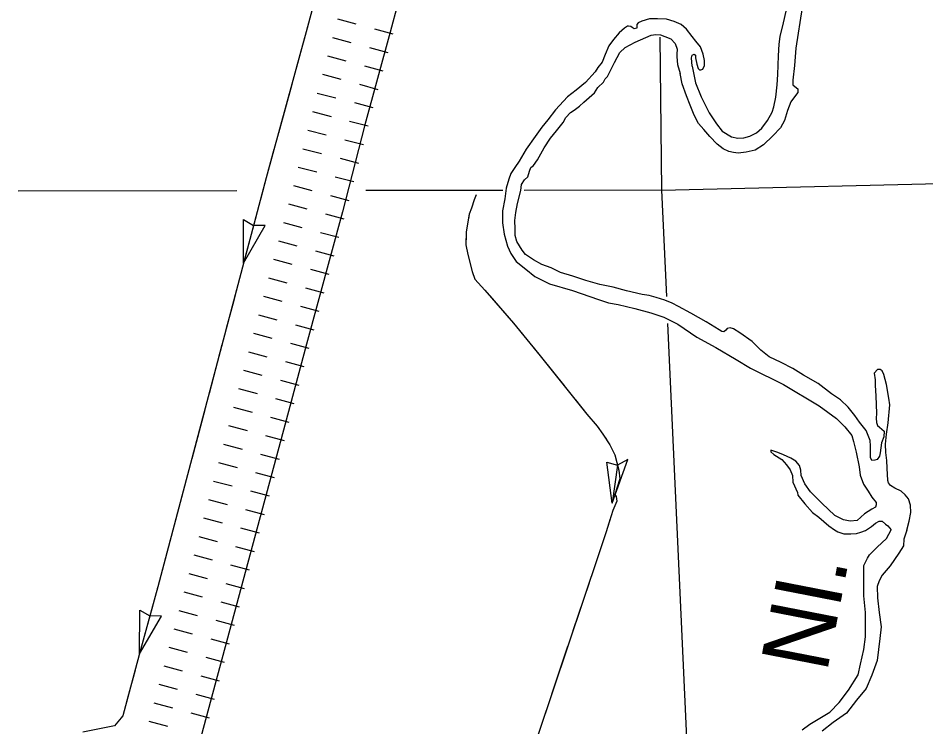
# Model space of a CAD drawing. Extents: x 1164457 to 1439835, y 1590918 to 1773502.
# Drawn here: x 1319420 to 1326531, y 1641151 to 1646706 of the extents above; entities that cross this region are included whole.
import ezdxf

# ---------------------------------------------------------------- set-up
doc = ezdxf.new("R2010")
doc.units = 0
for name, color, linetype in [('Level 29', 7, 'Continuous'), ('Level 35', 7, 'Continuous'), ('Level 43', 7, 'Continuous'), ('Level 5', 7, 'Continuous')]:
    doc.layers.add(name, color=color, linetype=linetype)

msp = doc.modelspace()

# ---------------------------------------------------------------- linework, layer by layer
at = {"layer": 'Level 29'}
for p, q in [((1321922, 1646700.6), (1322066.8, 1646661.2)), ((1322211.5, 1646621.8), (1322356.2, 1646582.4)), ((1321882.6, 1646555.9), (1322027.3, 1646516.5)), ((1321882.6, 1646555.9), (1322027.3, 1646516.5)), ((1322172.1, 1646477.1), (1322316.8, 1646437.7)), ((1322172.1, 1646477.1), (1322316.8, 1646437.7)), ((1321843.2, 1646411.1), (1321987.9, 1646371.7)), ((1322132.7, 1646332.3), (1322277.4, 1646292.9)), ((1321803.8, 1646266.4), (1321948.5, 1646227)), ((1322093.3, 1646187.6), (1322238, 1646148.2)), ((1321763.7, 1646118.7), (1321909, 1646081.3)), ((1321763.7, 1646118.7), (1321909, 1646081.3)), ((1322054.2, 1646043.8), (1322199.5, 1646006.4)), ((1322054.2, 1646043.8), (1322199.5, 1646006.4)), ((1321726.3, 1645973.5), (1321871.5, 1645936)), ((1322016.8, 1645898.6), (1322162, 1645861.1)), ((1321688.8, 1645828.2), (1321834.1, 1645790.8)), ((1321979.3, 1645753.3), (1322124.6, 1645715.9)), ((1321651.4, 1645683), (1321796.6, 1645645.5)), ((1321651.4, 1645683), (1321796.6, 1645645.5)), ((1321941.9, 1645608.1), (1322087.1, 1645570.6)), ((1321941.9, 1645608.1), (1322087.1, 1645570.6)), ((1321613.9, 1645537.7), (1321759.2, 1645500.3)), ((1321904.4, 1645462.8), (1322049.7, 1645425.4)), ((1321576.6, 1645395.1), (1321721.4, 1645356)), ((1321866.2, 1645316.9), (1322011, 1645277.8)), ((1321537.5, 1645250.3), (1321682.3, 1645211.2)), ((1321537.5, 1645250.3), (1321682.3, 1645211.2)), ((1321827.1, 1645172.1), (1321971.9, 1645133)), ((1321827.1, 1645172.1), (1321971.9, 1645133)), ((1321498.4, 1645105.4), (1321643.2, 1645066.4)), ((1321788, 1645027.3), (1321932.8, 1644988.2)), ((1321459.3, 1644960.6), (1321604.1, 1644921.5)), ((1321748.9, 1644882.4), (1321893.8, 1644843.4)), ((1321420.2, 1644815.8), (1321565, 1644776.7)), ((1321420.2, 1644815.8), (1321565, 1644776.7)), ((1321709.9, 1644737.6), (1321854.7, 1644698.5)), ((1321709.9, 1644737.6), (1321854.7, 1644698.5)), ((1321381.1, 1644671), (1321526, 1644631.9)), ((1321670.8, 1644592.8), (1321815.6, 1644553.7)), ((1321342.1, 1644526.2), (1321486.9, 1644487.1)), ((1321631.7, 1644448), (1321776.5, 1644408.9)), ((1321303, 1644381.3), (1321447.8, 1644342.3)), ((1321303, 1644381.3), (1321447.8, 1644342.3)), ((1321592.6, 1644303.2), (1321737.4, 1644264.1)), ((1321592.6, 1644303.2), (1321737.4, 1644264.1)), ((1321263.9, 1644236.5), (1321408.7, 1644197.4)), ((1321553.5, 1644158.4), (1321698.4, 1644119.3)), ((1321224.8, 1644091.7), (1321369.6, 1644052.6)), ((1321185.8, 1643946.9), (1321330.6, 1643907.8)), ((1321185.8, 1643946.9), (1321330.6, 1643907.8)), ((1321514.5, 1644013.5), (1321659.3, 1643974.5)), ((1321146.7, 1643802), (1321291.5, 1643763)), ((1321475.4, 1643868.7), (1321620.2, 1643829.6)), ((1321475.4, 1643868.7), (1321620.2, 1643829.6)), ((1321436.3, 1643723.9), (1321581.1, 1643684.8)), ((1321107.6, 1643657.1), (1321252.5, 1643618.1)), ((1321397.3, 1643579.1), (1321542.1, 1643540.1)), ((1321068.6, 1643512.3), (1321213.4, 1643473.3)), ((1321068.6, 1643512.3), (1321213.4, 1643473.3)), ((1321358.3, 1643434.3), (1321503.1, 1643395.2)), ((1321358.3, 1643434.3), (1321503.1, 1643395.2)), ((1321029.6, 1643367.5), (1321174.4, 1643328.4)), ((1321319.3, 1643289.4), (1321464.1, 1643250.4)), ((1320990.6, 1643222.6), (1321135.4, 1643183.6)), ((1321280.2, 1643144.6), (1321425.1, 1643105.6)), ((1320951.6, 1643077.8), (1321096.4, 1643038.8)), ((1320951.6, 1643077.8), (1321096.4, 1643038.8)), ((1321241.2, 1642999.7), (1321386.1, 1642960.7)), ((1321241.2, 1642999.7), (1321386.1, 1642960.7)), ((1320912.5, 1642932.9), (1321057.4, 1642893.9)), ((1321202.2, 1642854.9), (1321347, 1642815.9)), ((1320873.5, 1642788.1), (1321018.3, 1642749.1)), ((1321163.2, 1642710.1), (1321308, 1642671.1)), ((1320834.5, 1642643.3), (1320979.3, 1642604.3)), ((1320834.5, 1642643.3), (1320979.3, 1642604.3)), ((1321124.2, 1642565.2), (1321269, 1642526.2)), ((1321124.2, 1642565.2), (1321269, 1642526.2)), ((1320795.5, 1642498.4), (1320940.3, 1642459.4)), ((1321085.1, 1642420.4), (1321230, 1642381.4)), ((1320756.5, 1642353.6), (1320901.3, 1642314.6)), ((1321046.1, 1642275.6), (1321191, 1642236.5)), ((1320717.4, 1642208.8), (1320862.3, 1642169.7)), ((1320717.4, 1642208.8), (1320862.3, 1642169.7)), ((1321007.1, 1642130.7), (1321151.9, 1642091.7)), ((1321007.1, 1642130.7), (1321151.9, 1642091.7)), ((1320678.4, 1642063.9), (1320823.3, 1642024.9)), ((1320968.1, 1641985.9), (1321112.9, 1641946.9)), ((1320639.4, 1641919.1), (1320784.2, 1641880.1)), ((1320929.1, 1641841.1), (1321073.9, 1641802)), ((1320600.4, 1641774.3), (1320745.2, 1641735.2)), ((1320600.4, 1641774.3), (1320745.2, 1641735.2)), ((1320890.1, 1641696.2), (1321034.9, 1641657.2)), ((1320890.1, 1641696.2), (1321034.9, 1641657.2)), ((1320561.4, 1641629.4), (1320706.2, 1641590.4)), ((1320851, 1641551.4), (1320995.9, 1641512.4)), ((1320522.3, 1641484.6), (1320667.2, 1641445.6)), ((1320812, 1641406.6), (1320956.8, 1641367.5)), ((1320483.3, 1641339.8), (1320628.2, 1641300.7)), ((1320483.3, 1641339.8), (1320628.2, 1641300.7)), ((1320773, 1641261.7), (1320917.8, 1641222.7)), ((1320773, 1641261.7), (1320917.8, 1641222.7)), ((1320444.3, 1641194.9), (1320589.1, 1641155.9))]:
    msp.add_line(p, q, dxfattribs=at)
msp.add_lwpolyline([(1323235.6, 1649937.1), (1323120.9, 1649505.5), (1322642.8, 1647750), (1322454.2, 1647047.5), (1322333.9, 1646596.3), (1322136.2, 1645870), (1321960.1, 1645187), (1321680.3, 1644150.5), (1321509, 1643515.4), (1320784.9, 1640827.6), (1320738.7, 1640671.8), (1320728.4, 1640635.3), (1320716.3, 1640614.7), (1320699.4, 1640611), (1320619.9, 1640600.7)], dxfattribs=at)
at = {"layer": 'Level 35'}
for points in [[(1325561.6, 1646788.7), (1325512.1, 1646470.4), (1325502.9, 1646334.4), (1325490.5, 1646220.1), (1325490.5, 1646183), (1325505.9, 1646170.6), (1325527.6, 1646152.1), (1325527.6, 1646124.3), (1325502.1, 1646088.7), (1325472.7, 1646050.1), (1325448, 1645982.1), (1325423.3, 1645903.3), (1325394, 1645846.1), (1325333.7, 1645782.7), (1325259.6, 1645713.2), (1325193.1, 1645671.5), (1325123.6, 1645656), (1325061.8, 1645648.3), (1325023.2, 1645652.9), (1324989.2, 1645660.7), (1324942.9, 1645680.8), (1324896.5, 1645717.8), (1324839.4, 1645779.7), (1324791.5, 1645833.7), (1324751.3, 1645881.6), (1324715.8, 1645945), (1324684.9, 1646023.8), (1324655.6, 1646098), (1324621.6, 1646190.7), (1324607.7, 1646272.6)], [(1324700.4, 1646329.8), (1324726.6, 1646200), (1324769.9, 1646090.3), (1324834.8, 1645963.5), (1324891.9, 1645878.6), (1324935.2, 1645819.8), (1325007.8, 1645776.6), (1325058.7, 1645765.7), (1325106.6, 1645767.3), (1325151.4, 1645781.2), (1325205.5, 1645807.5), (1325245.7, 1645844.6), (1325292, 1645904.8), (1325327.5, 1645969.7), (1325341.4, 1646009.9), (1325356.9, 1646087.2), (1325367.7, 1646184.5), (1325370.8, 1646264.9), (1325377, 1646410.1), (1325381.6, 1646502.9), (1325389.3, 1646563.1), (1325415.6, 1646670.8), (1325451.1, 1646819.2)], [(1324700.4, 1646329.8), (1324696.6, 1646394.2), (1324699.7, 1646415.8), (1324715.2, 1646423.5), (1324726, 1646417.3), (1324727.5, 1646395.7), (1324736.8, 1646346.3), (1324747.6, 1646312.3), (1324756.9, 1646301.4), (1324769.2, 1646301.4), (1324784.7, 1646306.1), (1324798.6, 1646335.4), (1324798.6, 1646375.6), (1324787.8, 1646423.5), (1324766.1, 1646480.7), (1324730.6, 1646525.5), (1324699.7, 1646562.6), (1324656.5, 1646619.8), (1324613.2, 1646655.3), (1324559.1, 1646680), (1324498.9, 1646698.6), (1324429.4, 1646700.1), (1324367.6, 1646701.7), (1324307.3, 1646683.1), (1324276.4, 1646670.8), (1324267.2, 1646656.9), (1324267.2, 1646641.4), (1324267.2, 1646629), (1324247.1, 1646622.9), (1324231.6, 1646632.1), (1324219.3, 1646641.4), (1324200.7, 1646644.5), (1324193, 1646643), (1324169.9, 1646627.5), (1324128.1, 1646590.4), (1324084.9, 1646539.4), (1324047.8, 1646490), (1324020, 1646420.4), (1323995.3, 1646361.7), (1323961.3, 1646318.4), (1323939.7, 1646284.4), (1323864, 1646202.5), (1323791.4, 1646140.7), (1323723.4, 1646089.7), (1323629.2, 1645987.7), (1323570.5, 1645908.9), (1323523.4, 1645851.8), (1323470.8, 1645777.6), (1323401.3, 1645680.2), (1323344.2, 1645586), (1323310.2, 1645536.5), (1323279.3, 1645488.6), (1323263.9, 1645445.3), (1323242.2, 1645372.7), (1323233, 1645290.8), (1323216, 1645195), (1323214.4, 1645100.7), (1323226.8, 1645014.2), (1323253, 1644918.4), (1323279.3, 1644860.7), (1323321, 1644798.9), (1323396.7, 1644738.6), (1323467.8, 1644681.5), (1323583.6, 1644624.3), (1323764.3, 1644570.2), (1323968.1, 1644500.3), (1324045.1, 1644474.6), (1324122, 1644462), (1324251.7, 1644431.1), (1324376.8, 1644395.6), (1324478.6, 1644362.8), (1324588.5, 1644307.5), (1324738.3, 1644205.5), (1324886.6, 1644123.6), (1325045.7, 1644029.3), (1325158.5, 1643962.9), (1325417.1, 1643834.2), (1325696.7, 1643667.3), (1325831.1, 1643566.8), (1325896, 1643503.5), (1325951.6, 1643433.9), (1325965.5, 1643387.6), (1325985.6, 1643304.1), (1326010.3, 1643188.2), (1326016.4, 1643123.8), (1326042.7, 1643052.7), (1326079.8, 1642997.1), (1326109.1, 1642952.2), (1326141.6, 1642909), (1326143.1, 1642890.4), (1326136.9, 1642871.9), (1326107.6, 1642858), (1326052, 1642819.4), (1325993.3, 1642768.4), (1325937.7, 1642762.2), (1325886.7, 1642773), (1325818.7, 1642808.5), (1325716.8, 1642904.3), (1325627.2, 1642992.4), (1325582.4, 1643055.8), (1325554.6, 1643122.2)], [(1323542.3, 1645690.8), (1323590.2, 1645766.5), (1323636.6, 1645823.7), (1323689.1, 1645888.6), (1323710.7, 1645927.2), (1323746.3, 1645965.9), (1323775.6, 1645985.9), (1323818.9, 1646015.3), (1323852.8, 1646047.8), (1323934.7, 1646120.4), (1323962.5, 1646163.7), (1324005.8, 1646205.4), (1324018.1, 1646231.7), (1324038.2, 1646250.2), (1324053.7, 1646281.1), (1324092.3, 1646359.1), (1324134, 1646438), (1324175.7, 1646476.6), (1324254.5, 1646518.3), (1324379.6, 1646573.9), (1324415.1, 1646577), (1324453.8, 1646575.5), (1324487.7, 1646563.1), (1324534.8, 1646544.6), (1324568.8, 1646507.5), (1324582.7, 1646462.7), (1324579.6, 1646424.1), (1324579.6, 1646404), (1324585.8, 1646342.2), (1324607.7, 1646272.6)], [(1326382.6, 1642693.1), (1326401.1, 1642762.6), (1326413.4, 1642830.6), (1326411.9, 1642889.3), (1326394.9, 1642938.8), (1326368.6, 1642969.7), (1326339.3, 1642997.5), (1326288.3, 1643022.2), (1326254.3, 1643042.3), (1326238.9, 1643062.4), (1326234.3, 1643080.9), (1326229.6, 1643179.8), (1326225, 1643238.6), (1326217.3, 1643301.9), (1326215.7, 1643366.7), (1326221.9, 1643445.6), (1326237.3, 1643533.6), (1326249.7, 1643675.8), (1326240.4, 1643728.4), (1326223.4, 1643834.9), (1326201.8, 1643913.7), (1326189.5, 1643941.6), (1326172.5, 1643952.4), (1326153.9, 1643950.8), (1326127.7, 1643924.6), (1326133.8, 1643872), (1326133.8, 1643825.7), (1326138.5, 1643746.8), (1326144.7, 1643607.8), (1326143.1, 1643570.7), (1326144.7, 1643536.7), (1326153.9, 1643513.5), (1326169.4, 1643501.1), (1326204.9, 1643468.7), (1326201.8, 1643425.4), (1326183.3, 1643376), (1326174, 1643298.7), (1326169.4, 1643272.4), (1326149.3, 1643247.7), (1326132.3, 1643241.5), (1326109.1, 1643238.4), (1326098.3, 1643261.6), (1326098.3, 1643312.6), (1326098.3, 1643352.8), (1326095.2, 1643396.1), (1326062.8, 1643473.3), (1326011.8, 1643539.8), (1325974.7, 1643592.3), (1325923.8, 1643657.2), (1325863.5, 1643714.4), (1325793.2, 1643762.3), (1325686.6, 1643841.1), (1325572.3, 1643907.6), (1325488.9, 1643958.6), (1325397.8, 1644008), (1325305.1, 1644051.3), (1325238.7, 1644102.3), (1325170.7, 1644171.8), (1325073.4, 1644238.3), (1325023.9, 1644270.7), (1324997.7, 1644278.4), (1324976, 1644272.3), (1324965.2, 1644259.9), (1324948.2, 1644247.5), (1324932.8, 1644250.6), (1324912.7, 1644263), (1324810, 1644324.8), (1324689.5, 1644394.3), (1324593.7, 1644446.9), (1324544.3, 1644471.6), (1324487.1, 1644494.8), (1324419.2, 1644516.4), (1324363.5, 1644533.4), (1324307.9, 1644539.6), (1324187.4, 1644569), (1324080.9, 1644598.3), (1323977.4, 1644618.4), (1323868.3, 1644649.2), (1323766.3, 1644683.2), (1323669, 1644712.6), (1323594.9, 1644748.1), (1323523.8, 1644776), (1323457.4, 1644813), (1323395.6, 1644853.2), (1323367.8, 1644887.2), (1323347.7, 1644921.2), (1323327.6, 1644956), (1323313.7, 1645002.3), (1323315.3, 1645054.9), (1323312.2, 1645119.8), (1323319.9, 1645183.2), (1323332.3, 1645252.7), (1323358.5, 1645354.7), (1323364.7, 1645402.6), (1323386.3, 1645439.7), (1323412.6, 1645462.9), (1323426.5, 1645506.1), (1323437.3, 1645535.5), (1323457.4, 1645550.9), (1323489.8, 1645596.5), (1323542.3, 1645690.8)], [(1325554.6, 1643122.2), (1325551.5, 1643162.4), (1325542.2, 1643199.5), (1325512.9, 1643233.5), (1325472.7, 1643256.7), (1325415.5, 1643282.9), (1325370.7, 1643301.5), (1325316.7, 1643320), (1325316.7, 1643306.1), (1325339.8, 1643286), (1325403.2, 1643247.4), (1325438.7, 1643204.1), (1325469.6, 1643165.5), (1325486.6, 1643122.2), (1325489.7, 1643069.7), (1325525.2, 1642987.8), (1325528.3, 1642967.7), (1325582.4, 1642898.2), (1325642.6, 1642831.7), (1325693.6, 1642794.6), (1325772.4, 1642726.6), (1325815.6, 1642694.2), (1325841.9, 1642678.7), (1325888.2, 1642664.8), (1325917.6, 1642663.3), (1325943.8, 1642663.3), (1325988.6, 1642666.4), (1326022.6, 1642675.6), (1326058.2, 1642689.5), (1326104.5, 1642722), (1326136.9, 1642746.7), (1326164.7, 1642762.2), (1326187.9, 1642762.2), (1326215.7, 1642739), (1326232.7, 1642726.6), (1326259, 1642694.2)], [(1325561.3, 1641128.6), (1325622.6, 1641172.5), (1325701.5, 1641218.5), (1325780.3, 1641266.7), (1325851.5, 1641340.3), (1325926, 1641438.9), (1326000.5, 1641559.4), (1326020.2, 1641642.7), (1326046.5, 1641756.6), (1326059.6, 1641857.4), (1326059.6, 1641925.4), (1326059.6, 1642048.1), (1326046.5, 1642177.4), (1326046.5, 1642276), (1326046.5, 1642350.5), (1326046.5, 1642416.2), (1326074.9, 1642473.2), (1326090.3, 1642497.9), (1326149.4, 1642559.3), (1326223.9, 1642627.2), (1326241.4, 1642660.1), (1326259, 1642694.2)], [(1326382.6, 1642693.1), (1326359.8, 1642623.3), (1326357.6, 1642570.8), (1326320.3, 1642511.6), (1326252.4, 1642413), (1326188.9, 1642340.7), (1326164.8, 1642294.7), (1326149.5, 1642250.8), (1326151.7, 1642161), (1326164.8, 1642047.1), (1326180.2, 1641935.3), (1326171.4, 1641843.3), (1326149.5, 1641671.3), (1326107.9, 1641555.1), (1326064.1, 1641452.1), (1325987.4, 1641360.1), (1325910.7, 1641257.1), (1325805.6, 1641184.8), (1325720.2, 1641116.9)]]:
    msp.add_lwpolyline(points, dxfattribs=at)
at = {"layer": 'Level 43'}
for p, q in [((1321185.8, 1644784.3), (1321184.8, 1645127.5)), ((1321184.8, 1645127.5), (1321264, 1645082)), ((1321185.8, 1644784.3), (1321356.5, 1645082)), ((1321356.5, 1645082), (1321265.2, 1645081.7)), ((1324074.7, 1642904.9), (1324195.9, 1643247.5)), ((1324195.9, 1643247.5), (1324116.5, 1643202.4)), ((1324033, 1643226.2), (1324115.3, 1643202.1)), ((1324074.7, 1642904.9), (1324033, 1643226.2)), ((1320370.2, 1641723.1), (1320372.5, 1642066.3)), ((1320372.5, 1642066.3), (1320451.3, 1642020)), ((1320370.2, 1641723.1), (1320543.8, 1642019.1)), ((1320543.8, 1642019.1), (1320452.5, 1642019.7))]:
    msp.add_line(p, q, dxfattribs=at)
for points in [[(1322756.3, 1650581), (1322739.7, 1650522.6), (1322723.8, 1650470.3), (1322685.9, 1650354.9), (1322262.4, 1648781.4), (1322116.8, 1648218.6), (1321983.5, 1647746.9), (1321882.6, 1647370.8), (1321677.4, 1646598.8), (1321362.9, 1645453.3), (1320514.7, 1642248), (1320379.2, 1641755.6), (1320240.6, 1641236.7), (1320174.9, 1641157.6), (1319926, 1641108.5)], [(1321703.1, 1646695.5), (1321677.4, 1646598.8), (1321599, 1646313.4)], [(1321564.1, 1646186.1), (1321459.2, 1645804.2)], [(1321424.3, 1645676.9), (1321362.9, 1645453.3), (1321320.9, 1645294.7)], [(1323009, 1645322.1), (1322994.1, 1645281), (1322971.1, 1645217.6), (1322954.4, 1645168.6), (1322929.8, 1645031.8), (1322926.7, 1644929.2), (1322944, 1644853), (1322977.9, 1644720.5), (1322997.4, 1644660.5), (1323076.4, 1644574.4), (1323300.5, 1644316.3), (1323511, 1644058.1)], [(1323009, 1645322.1), (1322994.1, 1645281), (1322971.1, 1645217.6), (1322954.4, 1645168.6), (1322948.2, 1645134.1)], [(1321287.1, 1645167.1), (1321185.8, 1644784.3)], [(1322929, 1645003.7), (1322926.7, 1644929.2), (1322944, 1644853), (1322977.9, 1644720.5), (1322997.4, 1644660.5), (1323026.8, 1644628.5)], [(1321152.1, 1644656.6), (1321101.4, 1644465.2)], [(1323114.8, 1644530.2), (1323300.5, 1644316.3), (1323371.8, 1644228.9)], [(1321101.4, 1644465.2), (1321050.8, 1644273.8)], [(1321017, 1644146.2), (1320915.7, 1643763.4)], [(1323455.2, 1644126.6), (1323511, 1644058.1), (1323703.3, 1643818)], [(1323511, 1644058.1), (1323875.4, 1643603), (1323955.5, 1643506.9), (1324001, 1643445.5), (1324054.6, 1643360.4), (1324094.9, 1643282.7), (1324125.9, 1643163.5), (1324133.2, 1643094), (1324095.9, 1642973.4), (1324104.4, 1642956.4), (1324109.5, 1642920.7), (1324078.9, 1642847.7), (1324026.3, 1642679.6), (1323968.5, 1642506.3), (1323489.2, 1641076)], [(1323785.8, 1643714.9), (1323875.4, 1643603), (1323955.5, 1643506.9), (1324001, 1643445.5), (1324028.3, 1643402.3)], [(1320881.9, 1643635.8), (1320780.6, 1643253)], [(1324092.6, 1643287.1), (1324094.9, 1643282.7), (1324115.3, 1643202.1), (1324074.7, 1642904.9)], [(1320746.9, 1643125.4), (1320645.6, 1642742.5)], [(1324058.1, 1642781.4), (1324026.3, 1642679.6), (1323997.4, 1642592.9)], [(1320611.8, 1642614.9), (1320514.7, 1642248), (1320510.3, 1642232.1)], [(1323997.4, 1642592.9), (1323968.5, 1642506.3), (1323934.6, 1642405.1)], [(1323892.7, 1642280), (1323766.9, 1641904.5)], [(1320475.3, 1642104.9), (1320379.2, 1641755.6), (1320370.4, 1641723)], [(1323724.9, 1641779.4), (1323599.1, 1641403.9)], [(1320336.4, 1641595.5), (1320285.3, 1641404.2)], [(1320285.3, 1641404.2), (1320240.6, 1641236.7), (1320224.8, 1641217.7)], [(1323557.1, 1641278.7), (1323489.2, 1641076), (1323425, 1640905.5)]]:
    msp.add_lwpolyline(points, dxfattribs=at)
at = {"layer": 'Level 5'}
for points in [[(1324447.6, 1646557.7), (1324461.2, 1645358.2)], [(1324461.2, 1645358.2), (1327073.4, 1645421.8)], [(1321133, 1645353.2), (1319420.3, 1645350.6)], [(1323218.6, 1645356.3), (1322144, 1645354.7)], [(1324461.2, 1645358.2), (1323383.6, 1645356.5)], [(1324461.2, 1645358.2), (1324498.9, 1644524.3)], [(1324508.4, 1644313.6), (1324699.5, 1640091.8)]]:
    msp.add_lwpolyline(points, dxfattribs=at)

# ---------------------------------------------------------------- texts
at = {"layer": 'Level 35'}
msp.add_text('NI.', height=528, rotation=78.96388, dxfattribs=at).set_placement((1325755, 1641566.4))

doc.saveas('drawing.dxf')
